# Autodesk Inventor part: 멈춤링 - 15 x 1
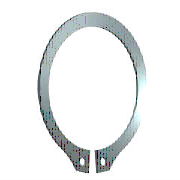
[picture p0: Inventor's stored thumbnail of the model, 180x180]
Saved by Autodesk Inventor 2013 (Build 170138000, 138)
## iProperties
Created: 2015-09
Part Number: 멈춤링 - 15 x 1
Material: 강, 연강
Description: 리테이닝 링(C형)
Document SubType Name: Modeling
Standard: KS B 1336
Designer: mm
Standards Organization: KS
Language: ko-KR
Size Designation: 15 x 1
Categories: <MemberInstance><Categories><Category DisplayName="샤프트 부품" InternalName="7f7aeb1f-a693-4053-b835-cee3144e0d98" Mnemonic="SHFT"><Category DisplayName="써클립" Inter
Density: 1 g/cm^3
IsCustomPart: 1
Author: mduedu
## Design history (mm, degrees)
sketch "스케치1"
  geometry: L1 (-6, 0)-(6, 0) reference; L2 (0, 20.189)-(0, -80.536) reference; L3 (-48.09, 0)-(48.09, 0) reference; L4 (-0.425, -14.637)-(-0.425, -18.137); L5 (-0.425, -6.54)-(-0.425, -13.29); L6 (-2.795, 2.1)-(3.672, 2.1); L7 (0.425, -6.54)-(0.425, -13.29); L8 (0.425, -14.637)-(0.425, -18.137); C1 r 0.85 at (-1.7, -16.283); C2 r 0.85 at (1.7, -16.283); A1 r 7.15 centre (0, -7.5) between (0.425, -14.637) and (-0.425, -14.637); A2 r 9.075 centre (0, -6.975) between (4.291, -14.971) and (-4.291, -14.971); A3 r 10.646 centre (0, -7.5) between (-2.023, -17.952) and (-0.425, -18.137); A4 r 1.7 centre (-1.7, -16.283) between (-3.397, -16.376) and (-2.023, -17.952); A5 r 1.7 centre (-5.095, -16.469) between (-3.397, -16.376) and (-4.291, -14.971); A6 r 1.7 centre (5.095, -16.469) between (4.291, -14.971) and (3.397, -16.376); A7 r 1.7 centre (1.7, -16.283) between (2.023, -17.952) and (3.397, -16.376); A8 r 10.646 centre (0, -7.5) between (0.425, -18.137) and (2.023, -17.952)
  constraints: 16 point on circle, 12 end point, 10 centre point, 9 symmetric about line, 5 point on line, 4 tangent, 3 coincident, 2 horizontal, 1 perpendicular, 1 vertical, 5 other
  dimensions: "d0" = 14.3 diameter of A1 (= ND); "d1" = 3.5 distance of L4.end L4.start (= SRB2); "d6" = 0.425 distance between parallel lines of L2 L5 (= 0.25 x SD5); "d7" = 2.1 distance between parallel lines of L6 L3 (= SRB1); "d8" = 0.525 distance of A1.centre A2.centre (= 0.25 x SRB1); "d9" = 1.7 radius of A4 (= SD5); "d10" = 1.7 radius of A5 (= SD5); "d11" = 1.275 distance from line of L4 A4.centre (= 0.75 x SD5); "d12" = 1.7 diameter of C1 (= SD5); "d13" = 1.7 diameter of C2 (= SD5); "d14" = 7.5 distance from line of A1.centre L1 (= 0.5 x WD)
extrude "본체" new body sketch "스케치1" distance "d2" = 1 (= SD); taper "d3" = 0 deg
workaxis "Work Axis1"
workplane "Work Plane1"
body "Solid1"
other parameters: "WD" = 15 (= WDMIN) [user parameter; used in 1 equation term], "SD" = 1 [user parameter; used in 1 equation term], "SRB1" = 2.1 [user parameter; used in 2 equation terms], "ND" = 14.3 [user parameter; used in 1 equation term], "SRB2" = 3.5 [user parameter; used in 1 equation term], "SD5" = 1.7 [user parameter; used in 6 equation terms], "d15" = 0, "d16" = 0, "d17" = 0, "d41" = 0, "d42" = 0, "WDMIN" = 15 [user parameter; used in 1 equation term], "SD3" = 13.8 [user parameter], "WDMAX" = 16 [user parameter]
